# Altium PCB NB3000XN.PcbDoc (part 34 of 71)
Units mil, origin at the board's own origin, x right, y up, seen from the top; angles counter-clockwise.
Board outline 9527.56 x 6929.77 mil, 6 copper layers (Top Layer, GND+SHIELD, MidLayer1, MidLayer2, P2 - 3V3+5V0, Bottom Layer), stack 62.375 mil thick; 832 components, 1027 nets, 4655 pads, 4981 vias.
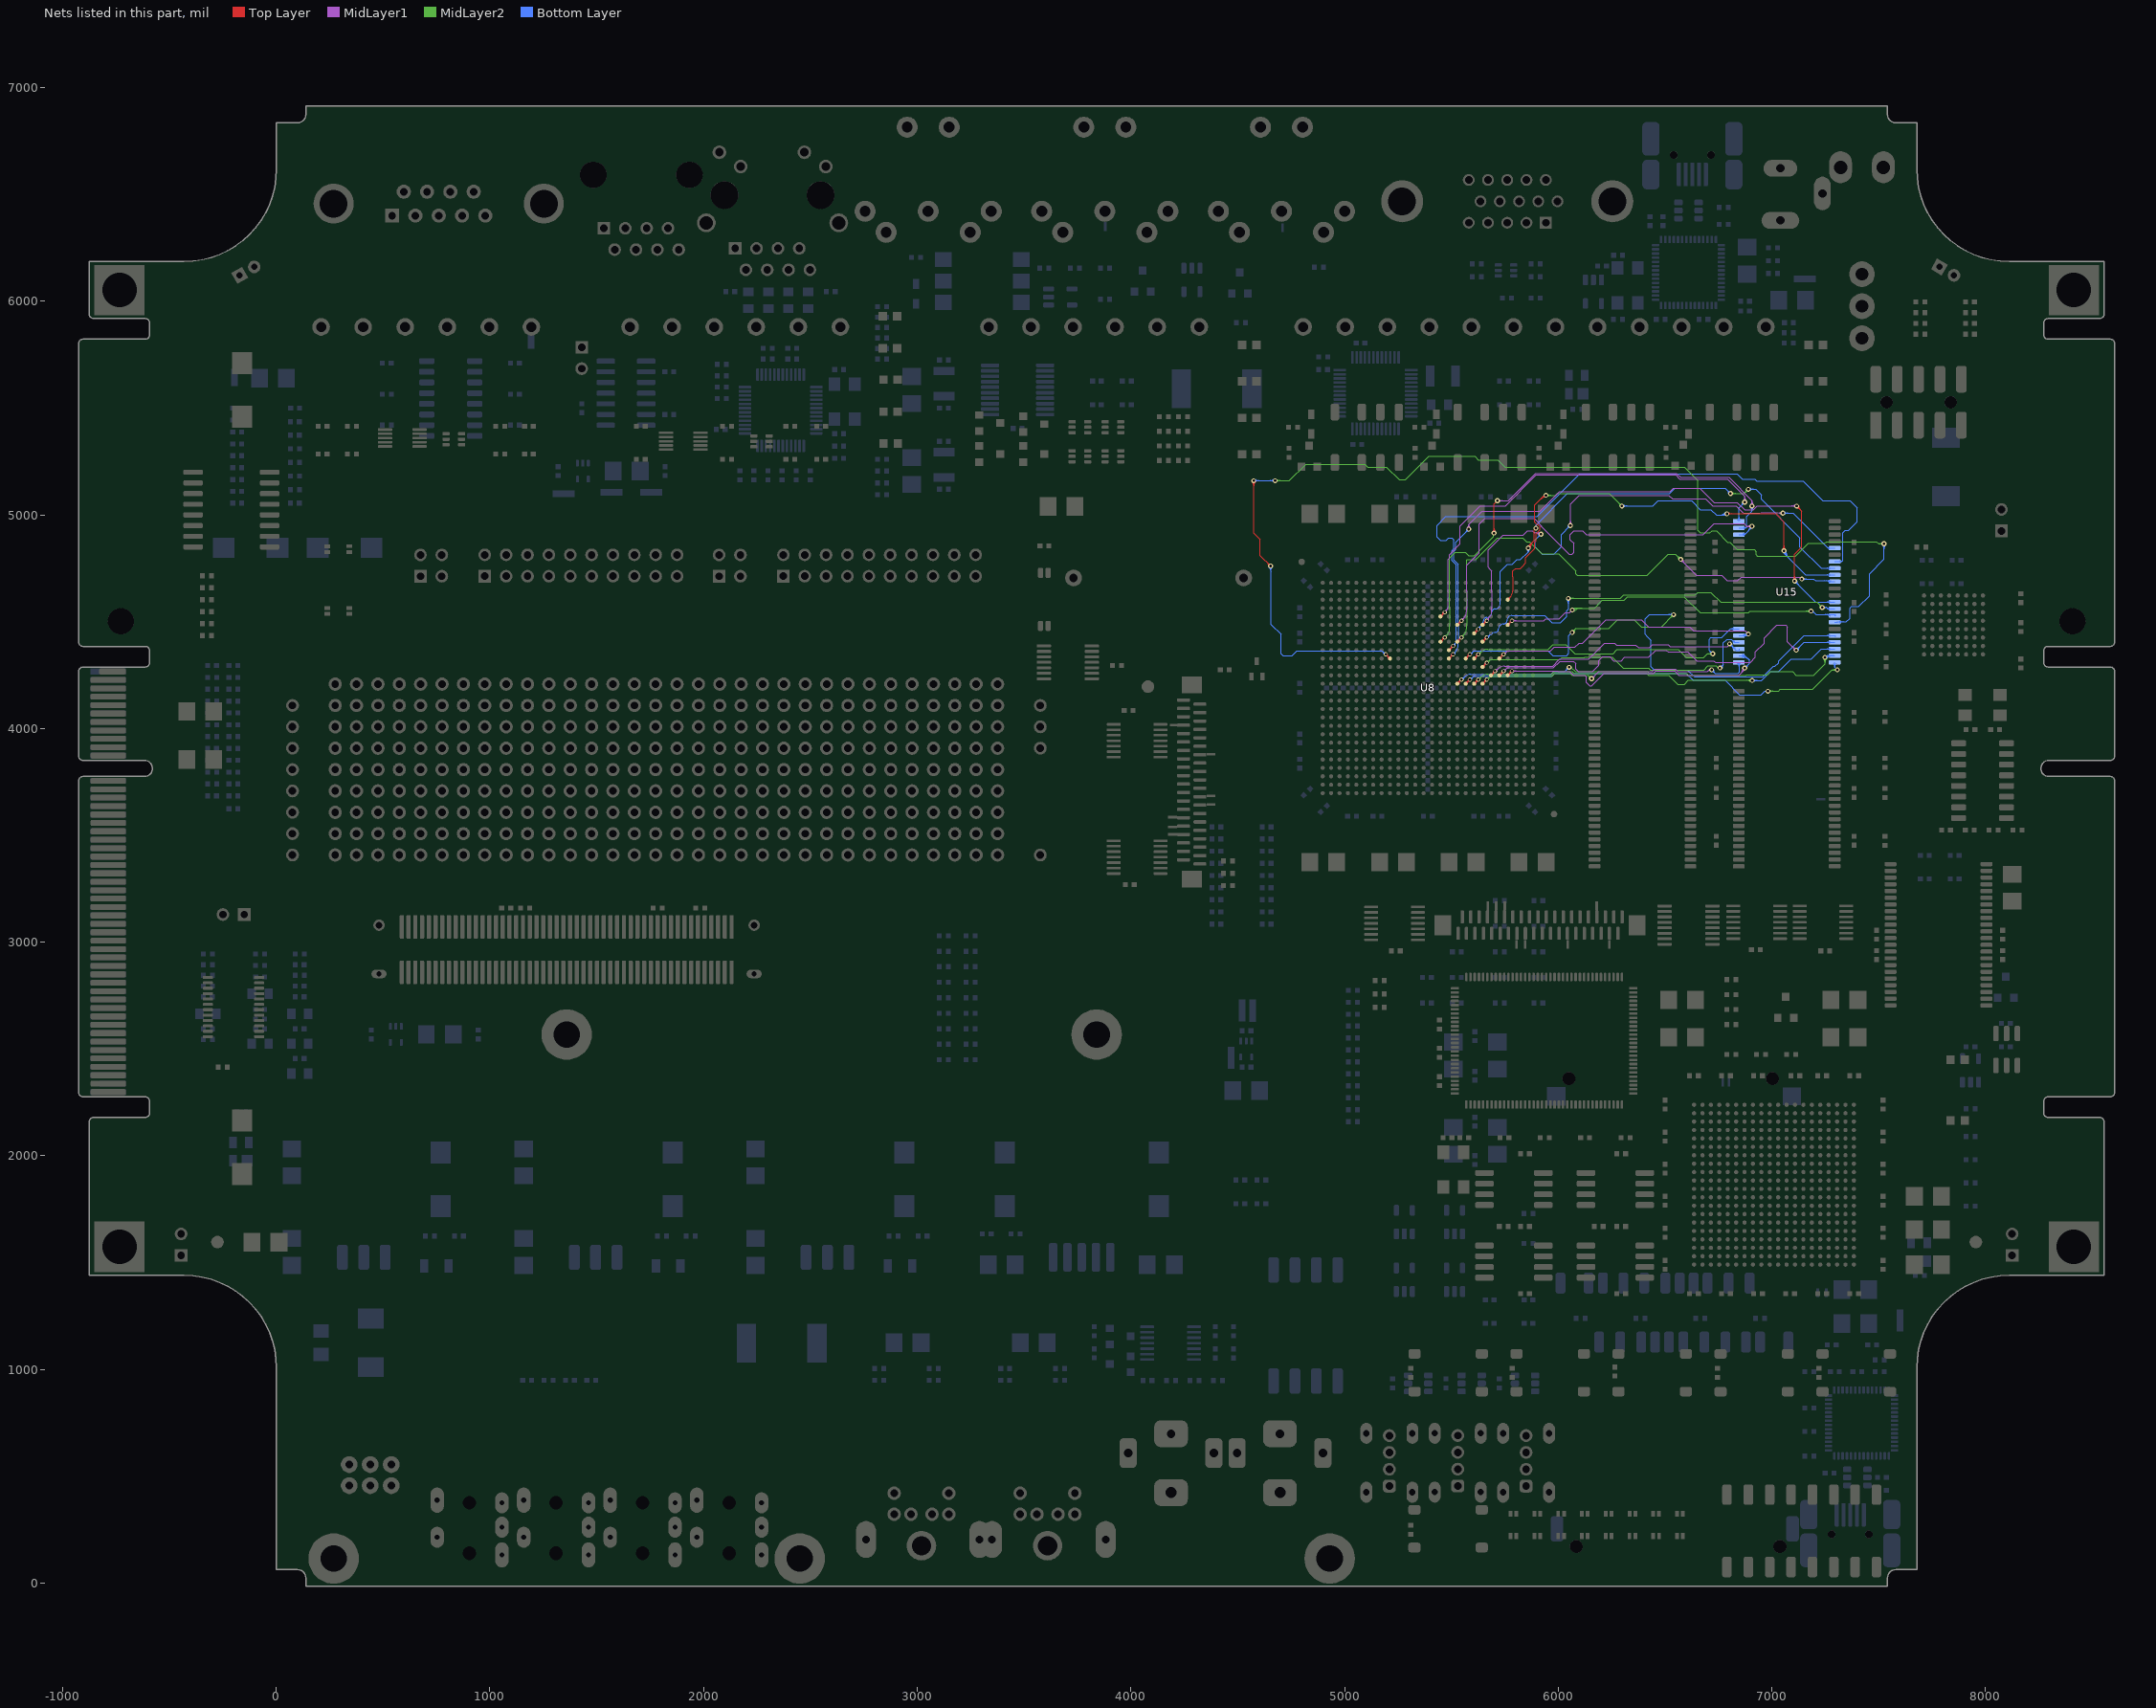
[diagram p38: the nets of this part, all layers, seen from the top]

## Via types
v1: diameter 23, hole 11.81, Top Layer to Bottom Layer, 3672 vias
v2: diameter 26, hole 11.81, Top Layer to Bottom Layer, 461 vias
v3: diameter 19, hole 11.81, Top Layer to Bottom Layer, tented both sides, 396 vias
v4: diameter 23.62, hole 11.81, Top Layer to Bottom Layer, 288 vias
v5: diameter 20, hole 11.81, Top Layer to Bottom Layer, 91 vias
v6: diameter 23, hole 11.81, Top Layer to Bottom Layer, tented both sides, 50 vias
v7: diameter 31, hole 11.81, Top Layer to Bottom Layer, 15 vias
v8: diameter 27.56, hole 11.81, Top Layer to Bottom Layer, tented both sides, 4 vias
v9: diameter 29, hole 11.81, Top Layer to Bottom Layer, 3 vias
v10: diameter 21, hole 11.81, Top Layer to Bottom Layer, 1 vias

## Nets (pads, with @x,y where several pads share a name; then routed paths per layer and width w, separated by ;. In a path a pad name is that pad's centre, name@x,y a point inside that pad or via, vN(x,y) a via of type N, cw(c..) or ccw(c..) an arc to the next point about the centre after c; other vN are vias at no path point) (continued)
DB_SRAM2.A4: U8.F20 U15.5 | length 2940.1
  Top Layer w4: U8.F20@5645.91,4485.28 v3(5665.59,4504.96) ; U8.F20@5645.91,4492.62 ccw(c5645.91,4510.34) 5658.44,4497.81 ccw(c5670.97,4485.28) U8.F20@5653.25,4485.28 ; U8.F20@5645.91,4492.78 ccw(c5645.91,4510.88) 5658.71,4498.08 ccw(c5671.51,4485.28) U8.F20@5653.41,4485.28 ; 5652.79,4492.16 cw(c5665.59,4479.35) 5665.59,4497.46 ccw(c5665.59,4479.35) 5652.79,4492.16 ; 5652.79,4492.16 ccw(c5639.98,4504.96) 5658.09,4504.96 cw(c5639.98,4504.96) 5652.79,4492.16
  MidLayer1 w4: v3@5664.29,4512.35 ccw(c5661.14,4530.18) 5675.98,4519.79 ; v3@5672.98,4506.26 cw(c5690.81,4509.41) 5675.98,4519.79 ; 5689.45,4581.77 5689.45,4567.84 ; 5896.15,4916.71 cw(c5896.15,4892.81) v1@5915.54,4906.78 ; 5903.96,4916.71 cw(c5903.96,4898.44) v1@5918.78,4909.12 ; v1@5912.29,4904.44 ccw(c5888.33,4887.17) 5888.33,4916.71 ; v1(5920,4910) 5920,4910.23 5913.52,4916.71 5888.33,4916.71 ; v1@6050.14,4956.76 ccw(c6032.37,4974.53) 6057.5,4974.53 ; v1@6052.97,4953.93 ccw(c6042.03,4964.87) 6057.5,4964.87 ; v1(6056.86,4950.04) 6057.5,4950.68 6057.5,5050.68 6098.52,5091.71 6518.17,5091.71 6534.84,5075.04 6690.19,5075.04 6723.52,5041.71 6831.86,5041.71 6865.86,5007.71 6944.52,5007.71 6948.52,5011.71 7030.04,5011.71 7033.37,5008.37 ; 6057.5,4961.77 ccw(c6068.58,4961.77) v1@6060.75,4953.93 ; 6057.5,4971.42 ccw(c6078.24,4971.42) v1@6063.57,4956.76 ; v1@7044.13,5002.85 ccw(c7033.38,4995.15) 7033.38,5008.37 ; v1@7044.13,5013.9 cw(c7033.38,5021.6) 7033.38,5008.37 ; v1(7051.86,5008.37) 7033.37,5008.37 ; 5675.98,4519.79 5683.06,4528.37 ccw(c5665.68,4544.59) 5689.45,4544.59 5689.45,4567.84 ; 5689.45,4567.84 5689.45,4641.96 5689.45,4661.38 5689.45,4710 5689.45,4720 5689.45,4724.74 5689.45,4737.45 5678.4,4748.5 5672.03,4754.87 5672.03,4835.25 5741.78,4905 5837.15,4905 5857.19,4925.04 5880,4925.04 5888.33,4916.71
  Bottom Layer w4: 5903.39,4893.62 cw(c5920,4877) v1@5920,4900.5 ; 5903.95,4894.18 ccw(c5888.13,4910) v1@5910.5,4910 ; 5910.21,4900.45 cw(c5920,4890.66) v1@5920,4904.5 ; 5910.77,4901.01 ccw(c5901.78,4910) v1@5914.5,4910 ; v1(5920,4910) 5920,4910.23 5892.61,4882.84 5892.61,4849.27 5925.17,4816.71 5979.88,4816.71 6015.52,4852.36 6015.52,4908.71 v1(6056.86,4950.04) ; v1@6047.36,4950.04 cw(c6024.42,4950.04) 6040.64,4933.82 cw(c6056.86,4917.61) v1@6056.86,4940.54 ; v1@6051.36,4950.04 cw(c6038.08,4950.04) 6047.47,4940.65 cw(c6056.86,4931.26) v1@6056.86,4944.54 ; v1(7051.86,5008.37) 7098.52,5008.37 7262.18,4844.72 ; v1@7055.75,5004.49 cw(c7065.14,4995.1) 7065.14,5008.37 cw(c7065.14,5021.65) v1@7055.75,5012.26 ; v1@7058.57,5001.66 cw(c7074.79,4985.44) 7074.79,5008.37 cw(c7074.79,5031.31) v1@7058.57,5015.09 ; U15.5@7270.13,4840.39 ccw(c7262.18,4835.27) 7262.18,4844.72 ; U15.5@7270.13,4849.06 cw(c7262.18,4854.18) 7262.18,4844.72 ; U15.5@7294.41,4844.72 7262.18,4844.72
DB_SRAM2.A5: U8.K18 U15.18 | length 2823.8
  Top Layer w4: U8.K18@5567.17,4327.8 v3(5586.85,4347.48) ; U8.K18@5567.17,4335.14 ccw(c5567.17,4352.86) 5579.7,4340.33 ccw(c5592.23,4327.8) U8.K18@5574.51,4327.8 ; U8.K18@5567.17,4335.3 ccw(c5567.17,4353.4) 5579.97,4340.6 ccw(c5592.77,4327.8) U8.K18@5574.67,4327.8 ; 5574.05,4334.68 cw(c5586.85,4321.87) 5586.85,4339.98 ccw(c5586.85,4321.87) 5574.05,4334.68 ; 5574.05,4334.68 ccw(c5561.24,4347.48) 5579.35,4347.48 cw(c5561.24,4347.48) 5574.05,4334.68
  MidLayer2 w4: v1(6065.19,4450.04) 6065.19,4451.04 6081.86,4467.71 ; v1@6065.19,4455.54 ccw(c6065.19,4466.4) 6072.87,4458.72 ; v1@6065.19,4459.54 ccw(c6065.19,4480.06) 6079.7,4465.55 ; v1@6070.69,4450.1 cw(c6085.85,4450.26) 6075.13,4460.98 ; v1@6074.69,4450.14 cw(c6099.16,4450.4) 6081.86,4467.71 ; v1@6530.69,4533.37 cw(c6507.76,4533.37) 6523.97,4517.16 cw(c6540.19,4500.94) v1@6540.19,4523.87 ; v1@6534.69,4533.37 cw(c6521.41,4533.37) 6530.8,4523.99 cw(c6540.19,4514.6) v1@6540.19,4527.87 ; v1(6540.19,4533.37) 6482.86,4476.04 6389.19,4476.04 6356.86,4508.37 6277.19,4508.37 6236.52,4467.71 6081.86,4467.71
  Bottom Layer w4: v3@5587.5,4354.95 ccw(c5589.08,4372.99) 5600.72,4359.12 ccw(c5612.36,4345.25) v3@5594.32,4346.83 ; 5600.43,4358.87 cw(c5610.36,4348.94) 5610.36,4362.99 5703.9,4362.99 5910,4362.99 5920,4362.99 5953.72,4362.99 5975,4341.71 6040.19,4341.71 6050,4351.52 6050,4434.85 v1(6065.19,4450.04) ; v1@6533.47,4526.66 ccw(c6517.26,4510.44) 6517.26,4533.37 ccw(c6517.26,4556.31) v1@6533.47,4540.09 ; v1@6536.3,4529.49 ccw(c6526.91,4520.1) 6526.91,4533.37 ccw(c6526.91,4546.65) v1@6536.3,4537.26 ; v1(6540.19,4533.37) 6428.37,4533.37 6407.72,4512.72 6407.72,4440.84 6415.23,4433.34 6435,4413.56 6435,4290 6450,4275 6604.88,4275 6637.17,4242.71 6957.86,4242.71 7006.86,4291.71 7015.19,4291.71 7031.86,4308.37 7031.86,4316.71 7141.26,4426.11 7150.42,4435.27 U15.18@7294.41,4435.27 7298.52,4435.28 7298.52,4433.37 U15.18@7294.41,4433.37 ; U15.18@7271.19,4429.62 ccw(c7257.54,4415.96) 7257.54,4435.27 ccw(c7257.54,4454.59) U15.18@7271.19,4440.93
DB_SRAM2.A6: U8.M22 U15.19 | length 2199.5
  Top Layer w4: U8.M22@5724.65,4249.06 v3(5744.33,4268.74) ; U8.M22@5724.65,4256.4 ccw(c5724.65,4274.12) 5737.18,4261.59 ccw(c5749.71,4249.06) U8.M22@5731.99,4249.06 ; U8.M22@5724.65,4256.56 ccw(c5724.65,4274.66) 5737.45,4261.86 ccw(c5750.25,4249.06) U8.M22@5732.15,4249.06 ; 5731.53,4255.94 cw(c5744.33,4243.13) 5744.33,4261.24 ccw(c5744.33,4243.13) 5731.53,4255.94 ; 5731.53,4255.94 ccw(c5718.72,4268.74) 5736.83,4268.74 cw(c5718.72,4268.74) 5731.53,4255.94
  MidLayer1 w4: v3@5744.98,4276.21 ccw(c5746.56,4294.25) 5758.2,4280.38 ccw(c5769.84,4266.51) v3@5751.8,4268.09 ; 5757.91,4280.13 cw(c5767.84,4270.2) 5767.84,4284.25 5861.38,4284.25 5910,4284.25 5920,4284.25 5978.06,4284.25 6007.86,4314.04 6072.52,4314.04 6081.86,4304.71 6081.86,4278.02 6093.5,4266.37 6161.19,4266.37 6190.19,4295.37 6190.19,4319.69 6205.5,4335 ; 6205.5,4335.71 6240.84,4335.71 6260.17,4316.37 6295.21,4316.37 6312.21,4333.37 6423.52,4333.37 6456.86,4366.71 6506.86,4366.71 6515.19,4358.37 6606.63,4358.37 6648.29,4316.71 6728.29,4316.71 6735.63,4309.37 6899.52,4309.37 6923.52,4333.37 6923.52,4358.37 6965.19,4400.04 6965.19,4425.04 7023.52,4483.37 7065.19,4483.37 7073.52,4475.04 7073.52,4407.04 v1(7113.86,4366.71) ; v1@7104.36,4366.71 ccw(c7081.42,4366.71) 7097.64,4382.93 ccw(c7113.86,4399.14) v1@7113.86,4376.21 ; v1@7108.36,4366.71 ccw(c7095.08,4366.71) 7104.47,4376.1 ccw(c7113.86,4385.49) v1@7113.86,4372.21
  Bottom Layer w4: v1(7113.86,4366.71) 7150.93,4403.78 U15.19@7293.97,4403.78 ; v1@7113.86,4372.21 ccw(c7113.86,4385.49) 7123.25,4376.1 ccw(c7132.64,4366.71) v1@7119.36,4366.71 ; v1@7113.86,4376.21 ccw(c7113.86,4399.14) 7130.07,4382.93 ccw(c7146.29,4366.71) v1@7123.36,4366.71 ; U15.19@7271.19,4398.12 ccw(c7257.54,4384.46) 7257.54,4403.78 ccw(c7257.54,4423.09) U15.19@7271.19,4409.44 ; U15.19@7293.97,4403.78 U15.19@7294.41,4403.78 U15.19@7293.97,4403.78
DB_SRAM2.A7: U8.N19 U15.20 | length 2062.7
  Top Layer w4: U8.N19@5606.54,4209.69 v3(5626.22,4229.37) ; U8.N19@5606.54,4217.03 ccw(c5606.54,4234.75) 5619.07,4222.22 ccw(c5631.6,4209.69) U8.N19@5613.88,4209.69 ; U8.N19@5606.54,4217.19 ccw(c5606.54,4235.29) 5619.34,4222.49 ccw(c5632.14,4209.69) U8.N19@5614.04,4209.69 ; 5613.42,4216.57 cw(c5626.22,4203.76) 5626.22,4221.87 ccw(c5626.22,4203.76) 5613.42,4216.57 ; 5613.42,4216.57 ccw(c5600.61,4229.37) 5618.72,4229.37 cw(c5600.61,4229.37) 5613.42,4216.57
  MidLayer2 w4: v3@5626.87,4236.84 ccw(c5628.45,4254.88) 5640.09,4241.01 ; v3@5633.69,4228.72 cw(c5651.73,4227.14) 5640.09,4241.01 ; 6422.96,4250 6422.92,4250.04 ; 6882.51,4226.04 cw(c6882.51,4199.69) v1@6901.14,4218.32 ; 6887.34,4226.04 ccw(c6887.34,4245.56) v1@6901.14,4231.76 ; 6892.16,4226.04 cw(c6892.16,4209.35) v1@6903.97,4221.15 ; v1(6907.86,4225.04) 6906.86,4226.04 6608.86,4226.04 6590.19,4207.37 6560.52,4207.37 6517.86,4250.04 6422.92,4250.04 ; 5640.09,4241.01 cw(c5669.6,4211.5) 5669.6,4253.23 5689.1,4253.23 5763.22,4253.23 5782.64,4253.23 5910,4253.23 5920,4253.23 5968.54,4253.23 5982.02,4266.71 6065.19,4266.71 6073.52,4258.37 6414.58,4258.37 6422.92,4250.04
  Bottom Layer w4: v1(6907.86,4225.04) 6952.19,4225.04 6993.52,4266.37 7031.52,4266.37 7090.19,4325.04 7184.62,4325.04 7231.86,4372.28 U15.20@7294.41,4372.28 ; v1@6911.75,4221.15 cw(c6921.14,4211.76) 6921.14,4225.04 cw(c6921.14,4238.32) v1@6911.75,4228.93 ; v1@6914.57,4218.32 cw(c6930.79,4202.11) 6930.79,4225.04 cw(c6930.79,4247.98) v1@6914.57,4231.76 ; U15.20@7271.19,4366.63 ccw(c7257.54,4352.97) 7257.54,4372.28 ccw(c7257.54,4391.6) U15.20@7271.19,4377.94
DB_SRAM2.A8: U8.N17 U15.21 | length 2255.6
  Top Layer w4: U8.N17@5527.8,4209.69 v3(5547.48,4229.37) ; U8.N17@5527.8,4217.03 ccw(c5527.8,4234.75) 5540.33,4222.22 ccw(c5552.86,4209.69) U8.N17@5535.14,4209.69 ; U8.N17@5527.8,4217.19 ccw(c5527.8,4235.29) 5540.6,4222.49 ccw(c5553.4,4209.69) U8.N17@5535.3,4209.69 ; 5534.68,4216.57 cw(c5547.48,4203.76) 5547.48,4221.87 ccw(c5547.48,4203.76) 5534.68,4216.57 ; 5534.68,4216.57 ccw(c5521.87,4229.37) 5539.98,4229.37 cw(c5521.87,4229.37) 5534.68,4216.57
  MidLayer2 w4: v1(6051.52,4287.04) 6059.19,4287.04 6079.52,4266.71 6370,4266.71 6417.56,4266.71 6425.9,4258.37 6599.86,4258.37 6609.86,4248.37 6879.52,4248.37 6881.86,4250.71 6977.86,4250.71 6993.86,4266.71 7096.19,4266.71 7112.86,4250.04 7195.19,4250.04 7248.52,4303.37 v1(7248.52,4333.37) ; v1@7241.81,4326.66 cw(c7225.59,4310.44) 7248.52,4310.44 cw(c7271.46,4310.44) v1@7255.24,4326.66 ; v1@7244.64,4329.49 cw(c7235.25,4320.1) 7248.52,4320.1 cw(c7261.8,4320.1) v1@7252.41,4329.49
  Bottom Layer w4: v3@5548.13,4236.84 ccw(c5549.71,4254.88) 5561.35,4241.01 ; v3@5554.95,4228.72 cw(c5572.99,4227.14) 5561.35,4241.01 ; v1@6042.02,4287.04 cw(c6019.09,4287.04) 6035.31,4270.82 cw(c6051.52,4254.61) v1@6051.52,4277.54 ; v1@6046.02,4287.04 cw(c6032.75,4287.04) 6042.13,4277.65 cw(c6051.52,4268.26) v1@6051.52,4281.54 ; v1(6051.52,4287.04) 6031.19,4266.71 5978.88,4266.71 5965.4,4253.23 5920,4253.23 5910,4253.23 5703.9,4253.23 5684.48,4253.23 5610.36,4253.23 5590.86,4253.23 ccw(c5590.86,4211.5) 5561.35,4241.01 ; v1@7246.76,4335.14 cw(c7260.38,4321.52) 7260.38,4340.79 ; v1(7248.52,4333.37) 7255.94,4340.79 U15.21@7294.41,4340.79 ; v1@7249.58,4332.31 cw(c7270.04,4311.86) U15.21@7270.04,4340.79 ; v1@7252.41,4329.49 cw(c7279.7,4302.2) U15.21@7279.7,4340.79 ; v1@7255.24,4326.66 cw(c7289.35,4292.55) U15.21@7289.35,4340.79 ; U15.21@7271.19,4335.13 ccw(c7257.54,4321.47) 7257.54,4340.79 ccw(c7257.54,4360.1) U15.21@7271.19,4346.44
DB_SRAM2.A9: U8.N18 U15.22 | length 2155.8
  Top Layer w4: U8.N18@5567.17,4209.69 v3(5586.85,4229.37) ; U8.N18@5567.17,4217.03 ccw(c5567.17,4234.75) 5579.7,4222.22 ccw(c5592.23,4209.69) U8.N18@5574.51,4209.69 ; U8.N18@5567.17,4217.19 ccw(c5567.17,4235.29) 5579.97,4222.49 ccw(c5592.77,4209.69) U8.N18@5574.67,4209.69 ; 5574.05,4216.57 cw(c5586.85,4203.76) 5586.85,4221.87 ccw(c5586.85,4203.76) 5574.05,4216.57 ; 5574.05,4216.57 ccw(c5561.24,4229.37) 5579.35,4229.37 cw(c5561.24,4229.37) 5574.05,4216.57
  MidLayer2 w4: v1(6981.86,4175.04) 7031.67,4175.04 7040,4183.37 7190.19,4183.37 7281.86,4275.04 v1(7306.86,4275.04) ; v1@6985.75,4171.15 cw(c6995.14,4161.76) 6995.14,4175.04 cw(c6995.14,4188.32) v1@6985.75,4178.93 ; v1@6988.57,4168.32 cw(c7004.79,4152.11) 7004.79,4175.04 cw(c7004.79,4197.98) v1@6988.57,4181.76 ; v1@7300.14,4268.32 ccw(c7283.92,4252.11) 7283.92,4275.04 ccw(c7283.92,4297.98) v1@7300.14,4281.76 ; v1@7302.97,4271.15 ccw(c7293.58,4261.76) 7293.58,4275.04 ccw(c7293.58,4288.32) v1@7302.97,4278.93
  Bottom Layer w4: v3@5587.5,4236.84 ccw(c5589.08,4254.88) 5600.72,4241.01 ccw(c5612.36,4227.14) v3@5594.32,4228.72 ; 5600.43,4240.76 cw(c5610.36,4230.83) 5610.36,4244.88 5703.9,4244.88 5910,4244.88 5920,4244.88 5924.74,4244.88 5968.36,4244.88 5981.86,4258.37 6598.88,4258.37 6631.21,4226.04 6780.86,4226.04 6848.52,4158.37 6950,4158.37 6966.67,4175.04 v1(6981.86,4175.04) ; U15.22@7288.75,4303.63 cw(c7275.1,4289.98) 7294.41,4289.98 cw(c7313.72,4289.98) U15.22@7300.07,4303.63 ; U15.22@7294.41,4309.29 7294.41,4287.49 v1(7306.86,4275.04)
DB_SRAM2.A10: U8.N20 U15.23 | length 1706.8
  Top Layer w4: U8.N20@5645.91,4209.69 v3(5665.59,4229.37) ; U8.N20@5645.91,4217.03 ccw(c5645.91,4234.75) 5658.44,4222.22 ccw(c5670.97,4209.69) U8.N20@5653.25,4209.69 ; U8.N20@5645.91,4217.19 ccw(c5645.91,4235.29) 5658.71,4222.49 ccw(c5671.51,4209.69) U8.N20@5653.41,4209.69 ; 5652.79,4216.57 cw(c5665.59,4203.76) 5665.59,4221.87 ccw(c5665.59,4203.76) 5652.79,4216.57 ; 5652.79,4216.57 ccw(c5639.98,4229.37) 5658.09,4229.37 cw(c5639.98,4229.37) 5652.79,4216.57
  MidLayer1 w4: v1(6156.86,4233.37) 6190.19,4266.71 6441.71,4266.71 6453.54,4278.54 6548.01,4278.54 6559.84,4266.71 6698.52,4266.71 6706.86,4275.04 v1(6718.19,4275.04) ; v1@6156.86,4238.87 ccw(c6156.86,4252.15) 6166.25,4242.76 ccw(c6175.64,4233.37) v1@6162.36,4233.37 ; v1@6156.86,4242.87 ccw(c6156.86,4265.81) 6173.07,4249.59 ccw(c6189.29,4233.37) v1@6166.36,4233.37 ; 6697.35,4265.53 cw(c6710.29,4252.6) v1@6716.36,4269.85 ; 6701.84,4270.02 cw(c6712.63,4259.24) v1@6717.69,4273.63 ; 6706.33,4274.52 cw(c6714.97,4265.88) v1@6719.02,4277.4
  MidLayer2 w4: v3@5666.24,4236.84 ccw(c5667.82,4254.88) 5679.46,4241.01 ccw(c5691.1,4227.14) v3@5673.06,4228.72 ; 5679.17,4240.76 cw(c5689.1,4230.83) 5689.1,4244.88 5782.64,4244.88 5910,4244.88 5920,4244.88 5971.5,4244.88 5985,4258.37 6056.86,4258.37 6065.19,4250.04 6115,4250.04 6140.23,4250 v1(6156.86,4233.37) ; v1@6147.36,4233.37 ccw(c6124.42,4233.37) 6140.64,4249.59 ccw(c6156.86,4265.81) v1@6156.86,4242.87 ; v1@6151.36,4233.37 ccw(c6138.08,4233.37) 6147.47,4242.76 ccw(c6156.86,4252.15) v1@6156.86,4238.87
  Bottom Layer w4: v1@6718.19,4265.54 cw(c6718.19,4242.61) 6734.41,4258.82 cw(c6750.63,4275.04) v1@6727.69,4275.04 ; v1@6718.19,4269.54 cw(c6718.19,4256.26) 6727.58,4265.65 cw(c6736.97,4275.04) v1@6723.69,4275.04 ; v1(6718.19,4275.04) 6734.52,4258.71 6841.29,4258.71 6848.52,4265.94 6848.52,4309.29 U15.23@6845.59,4309.29 ; U15.23@6839.93,4303.63 cw(c6819.19,4282.89) 6848.52,4282.89 ; U15.23@6842.76,4306.46 cw(c6828.85,4292.55) 6848.52,4292.55 ; 6848.52,4297.06 cw(c6857.82,4297.06) U15.23@6851.25,4303.63
DB_SRAM2.A11: U8.M23 U15.24 | length 1719.9
  Top Layer w4: U8.M23@5764.02,4249.06 v3(5783.7,4268.74) ; U8.M23@5764.02,4256.4 ccw(c5764.02,4274.12) 5776.55,4261.59 ccw(c5789.08,4249.06) U8.M23@5771.36,4249.06 ; U8.M23@5764.02,4256.56 ccw(c5764.02,4274.66) 5776.82,4261.86 ccw(c5789.62,4249.06) U8.M23@5771.52,4249.06 ; 5770.9,4255.94 cw(c5783.7,4243.13) 5783.7,4261.24 ccw(c5783.7,4243.13) 5770.9,4255.94 ; 5770.9,4255.94 ccw(c5758.09,4268.74) 5776.2,4268.74 cw(c5758.09,4268.74) 5770.9,4255.94
  MidLayer1 w4: v3(5783.7,4268.74) 5861.38,4268.74 5910,4268.74 5920,4268.74 5997.97,4268.74 6000,4266.71 6053.86,4266.71 6070.52,4250.04 6123.86,4250.04 6131.86,4242.04 6131.86,4216.71 6148.52,4200.04 6156.86,4200.04 6215.19,4258.37 6444.69,4258.37 6456.85,4270.54 6544.7,4270.54 6545.52,4269.71 6565.19,4250.04 6846.86,4250.04 6873.52,4276.71 v1(6873.52,4283.37) ; v3@5788.89,4263.55 cw(c5801.43,4251.01) 5801.43,4268.74 cw(c5801.43,4286.47) v3@5788.89,4273.93 ; v3@5789,4263.44 cw(c5801.81,4250.63) 5801.81,4268.74 cw(c5801.81,4286.85) v3@5789,4274.04 ; 6852.59,4255.78 ccw(c6824.99,4283.37) v1@6864.02,4283.37 ; 6859.42,4262.6 ccw(c6838.65,4283.37) v1@6868.02,4283.37 ; 6866.25,4269.43 ccw(c6852.31,4283.37) v1@6872.02,4283.37 ; 6868.69,4271.87 cw(c6873.52,4267.04) v1@6873.52,4273.87
  Bottom Layer w4: U15.24@6845.59,4340.79 6874.21,4340.79 6895,4320 6895,4304.85 v1(6873.52,4283.37) ; U15.24@6863.15,4332.79 cw(c6863.15,4286.76) 6895.69,4319.31 ; U15.24@6863.15,4336.79 cw(c6863.15,4300.42) 6888.86,4326.14 ; U15.24@6863.15,4340.79 cw(c6863.15,4314.08) 6882.04,4332.96 ; U15.24@6863.15,4344.79 cw(c6863.15,4327.73) 6875.21,4339.79 ; v1@6873.52,4288.87 ccw(c6873.52,4302.15) 6882.91,4292.76 ccw(c6892.3,4283.37) v1@6879.02,4283.37 ; v1@6873.52,4292.87 ccw(c6873.52,4315.81) 6889.74,4299.59 ccw(c6905.96,4283.37) v1@6883.02,4283.37
DB_SRAM2.A12: U8.M21 U15.25 | length 1505.3
  Top Layer w4: U8.M21@5685.28,4249.06 v3(5704.96,4268.74) ; U8.M21@5685.28,4256.4 ccw(c5685.28,4274.12) 5697.81,4261.59 ccw(c5710.34,4249.06) U8.M21@5692.62,4249.06 ; U8.M21@5685.28,4256.56 ccw(c5685.28,4274.66) 5698.08,4261.86 ccw(c5710.88,4249.06) U8.M21@5692.78,4249.06 ; 5692.16,4255.94 cw(c5704.96,4243.13) 5704.96,4261.24 ccw(c5704.96,4243.13) 5692.16,4255.94 ; 5692.16,4255.94 ccw(c5679.35,4268.74) 5697.46,4268.74 cw(c5679.35,4268.74) 5692.16,4255.94
  MidLayer1 w4: v3@5705.61,4276.21 ccw(c5707.19,4294.25) 5718.83,4280.38 ; v3@5712.43,4268.09 cw(c5730.47,4266.51) 5718.83,4280.38 ; 5781.77,4292.6 5767.84,4292.6 ; v1(6802.19,4396.71) 6802.19,4391.71 6793.69,4383.21 6524.3,4383.21 6515.8,4391.71 6441.88,4391.71 6428.54,4378.37 6375.84,4378.37 6363.17,4391.04 6273.52,4391.04 6265.19,4399.37 6217.5,4399.37 6143.17,4325.04 6007.52,4325.04 5975.09,4292.6 5920,4292.6 5910,4292.6 5861.38,4292.6 5841.96,4292.6 5767.84,4292.6 ; 5718.83,4280.38 cw(c5748.34,4250.87) 5748.34,4292.6 5767.84,4292.6
  Bottom Layer w4: v1@6802.19,4387.21 cw(c6802.19,4364.27) 6818.41,4380.49 cw(c6834.63,4396.71) v1@6811.69,4396.71 ; v1@6802.19,4391.21 cw(c6802.19,4377.93) 6811.58,4387.32 cw(c6820.97,4396.71) v1@6807.69,4396.71 ; v1(6802.19,4396.71) 6832.19,4366.71 6845.59,4366.71 6848.52,4366.71 6848.52,4372.28 U15.25@6845.59,4372.28 ; 6811.96,4386.94 ccw(c6828.03,4403.02) U15.25@6828.03,4380.28 ; 6815.38,4383.52 cw(c6804.14,4372.28) U15.25@6820.03,4372.28 ; 6818.79,4380.11 ccw(c6828.03,4389.36) U15.25@6828.03,4376.28
DB_SRAM2.A13: U8.L20 U15.26 | length 1585.2
  Top Layer w4: U8.L20@5645.91,4288.43 v3(5665.59,4308.11) ; U8.L20@5645.91,4295.77 ccw(c5645.91,4313.49) 5658.44,4300.96 ccw(c5670.97,4288.43) U8.L20@5653.25,4288.43 ; U8.L20@5645.91,4295.93 ccw(c5645.91,4314.03) 5658.71,4301.23 ccw(c5671.51,4288.43) U8.L20@5653.41,4288.43 ; 5652.79,4295.31 cw(c5665.59,4282.5) 5665.59,4300.61 ccw(c5665.59,4282.5) 5652.79,4295.31 ; 5652.79,4295.31 ccw(c5639.98,4308.11) 5658.09,4308.11 cw(c5639.98,4308.11) 5652.79,4295.31
  MidLayer2 w4: v3@5666.24,4315.58 ccw(c5667.82,4333.62) 5679.46,4319.75 ccw(c5691.1,4305.88) v3@5673.06,4307.46 ; 5679.17,4319.5 cw(c5689.1,4309.57) 5689.1,4323.62 5782.64,4323.62 5910,4323.62 5920,4323.62 5924.74,4323.62 6008.43,4323.62 6017.52,4332.71 6123.19,4332.71 6125.19,4334.71 6252.19,4334.71 6303.52,4283.37 6423.52,4283.37 6431.86,4275.04 6681.86,4275.04 6700.19,4293.37 6738.52,4293.37 6748.52,4283.37 v1(6757.52,4283.37)
  Bottom Layer w4: v1(6757.52,4283.37) 6773.52,4299.37 ; v1@6757.58,4288.87 ccw(c6757.7,4301.72) 6766.79,4292.64 ccw(c6775.87,4283.55) v1@6763.02,4283.43 ; v1@6757.62,4292.87 ccw(c6757.83,4315.07) 6773.52,4299.37 ; v1@6767.02,4283.47 cw(c6789.22,4283.68) 6773.52,4299.37 ; 6812.39,4414.66 ccw(c6821.68,4423.95) U15.26@6825.63,4411.41 ; 6817.05,4409.99 ccw(c6823.92,4416.86) U15.26@6826.83,4407.59 ; 6817.75,4409.29 cw(c6812.23,4403.78) U15.26@6820.03,4403.78 ; U15.26@6845.59,4403.78 6823.26,4403.78 6810,4417.04 6789.52,4417.04 6773.52,4401.04 6773.52,4299.37
DB_SRAM2.A14: U8.K22 U15.27 | length 1574.5
  Top Layer w4: U8.K22@5724.65,4327.8 v3(5744.33,4347.48) ; U8.K22@5724.65,4335.14 ccw(c5724.65,4352.86) 5737.18,4340.33 ccw(c5749.71,4327.8) U8.K22@5731.99,4327.8 ; U8.K22@5724.65,4335.3 ccw(c5724.65,4353.4) 5737.45,4340.6 ccw(c5750.25,4327.8) U8.K22@5732.15,4327.8 ; 5731.53,4334.68 cw(c5744.33,4321.87) 5744.33,4339.98 ccw(c5744.33,4321.87) 5731.53,4334.68 ; 5731.53,4334.68 ccw(c5718.72,4347.48) 5736.83,4347.48 cw(c5718.72,4347.48) 5731.53,4334.68
  MidLayer1 w4: v3@5744.98,4354.95 ccw(c5746.56,4372.99) 5758.2,4359.12 ccw(c5769.84,4345.25) v3@5751.8,4346.83 ; 5757.91,4358.87 cw(c5767.84,4348.94) 5767.84,4362.99 5861.38,4362.99 5910,4362.99 5920,4362.99 5964.39,4362.99 5982.11,4380.71 6079.19,4380.71 6098.52,4400.04 6115.19,4400.04 6223.52,4508.37 6390.19,4508.37 6422.52,4476.04 6615.19,4476.04 6632.86,4458.37 6874.52,4458.37 v1(6890.19,4442.71)
  Bottom Layer w4: U15.27@6845.59,4435.27 6882.76,4435.27 v1(6890.19,4442.71) ; U15.27@6849.31,4435.27 ccw(c6849.31,4483.59) v1@6883.47,4449.43 ; U15.27@6858.97,4435.27 ccw(c6858.97,4473.93) v1@6886.3,4446.6 ; U15.27@6868.62,4435.27 ccw(c6868.62,4464.27) v1@6889.13,4443.77 ; U15.27@6868.81,4429.62 cw(c6882.46,4415.96) 6882.46,4435.27 cw(c6882.46,4454.59) U15.27@6868.81,4440.93 ; 6878.28,4435.27 ccw(c6878.28,4454.62) v1@6891.96,4440.94
DB_SRAM2.A15: U8.F17 U15.42 | length 2387
  Top Layer w4: U8.F17@5527.8,4485.28 v3(5547.48,4504.96) ; U8.F17@5527.8,4492.62 ccw(c5527.8,4510.34) 5540.33,4497.81 ccw(c5552.86,4485.28) U8.F17@5535.14,4485.28 ; U8.F17@5527.8,4492.78 ccw(c5527.8,4510.88) 5540.6,4498.08 ccw(c5553.4,4485.28) U8.F17@5535.3,4485.28 ; 5534.68,4492.16 cw(c5547.48,4479.35) 5547.48,4497.46 ccw(c5547.48,4479.35) 5534.68,4492.16 ; 5534.68,4492.16 ccw(c5521.87,4504.96) 5539.98,4504.96 cw(c5521.87,4504.96) 5534.68,4492.16
  MidLayer1 w4: v3@5546.83,4512.43 ccw(c5545.25,4530.47) 5559.12,4518.83 ; v3@5554.95,4505.61 cw(c5572.99,4507.19) 5559.12,4518.83 ; 5571.34,4581.77 5571.34,4567.84 ; v1@6900.14,4939.99 ccw(c6883.92,4923.77) 6883.92,4946.71 ccw(c6883.92,4969.64) v1@6900.14,4953.43 ; v1@6902.97,4942.82 ccw(c6893.58,4933.43) 6893.58,4946.71 ccw(c6893.58,4959.99) v1@6902.97,4950.6 ; v1(6906.86,4946.71) 6882.92,4946.71 6871.25,4958.37 6728.86,4958.37 6678.86,4908.37 6131.86,4908.37 6115.19,4925.04 6073.52,4925.04 6056.86,4908.37 6056.86,4883.71 6073.52,4867.04 6073.52,4824.71 6065.52,4816.71 6051.52,4816.71 5921.81,4946.42 5921.81,4948.57 5887.01,4983.37 5658.37,4983.37 5631.02,4956.02 5631.02,4823.37 5571.34,4763.69 5571.34,4724.74 5571.34,4720 5571.34,4710 5571.34,4661.38 5571.34,4641.96 5571.34,4567.84 ; 5559.12,4518.83 ccw(c5529.61,4548.34) 5571.34,4548.34 5571.34,4567.84
  Bottom Layer w4: U15.42@6845.59,4907.72 6873.15,4907.72 6881.15,4915.72 ; U15.42@6863.15,4907.72 ccw(c6868.03,4915.04) 6874.25,4908.82 ; U15.42@6865.37,4911.04 ccw(c6870.79,4919.18) 6877.7,4912.27 ; U15.42@6867.59,4914.37 ccw(c6873.55,4923.32) 6881.15,4915.72 ; 6888.05,4924.23 ccw(c6865.57,4946.71) v1@6897.36,4946.71 ; 6894.88,4931.06 ccw(c6879.23,4946.71) v1@6901.36,4946.71 ; 6896.9,4933.08 cw(c6906.86,4923.13) v1@6906.86,4937.21 ; v1(6906.86,4946.71) 6906.86,4943.04 6881.15,4917.33 6881.15,4915.72
DB_SRAM2.A16: U8.H15 U15.43 | length 2748.8
  Top Layer w4: U8.H15@5449.06,4406.54 v3(5468.74,4426.22) ; U8.H15@5449.06,4413.88 ccw(c5449.06,4431.6) 5461.59,4419.07 ccw(c5474.12,4406.54) U8.H15@5456.4,4406.54 ; U8.H15@5449.06,4414.04 ccw(c5449.06,4432.14) 5461.86,4419.34 ccw(c5474.66,4406.54) U8.H15@5456.56,4406.54 ; v1@5693.28,4921.72 ccw(c5677.06,4937.93) 5700,4937.93 ccw(c5722.93,4937.93) v1@5706.72,4921.72 ; v1@5696.11,4918.89 ccw(c5686.72,4928.28) 5700,4928.28 ccw(c5713.28,4928.28) v1@5703.89,4918.89 ; v1@5698.52,4915.71 5699.23,4915 v1(5700,4915) 5700,5051.52 v1(5715.19,5066.71) ; 5455.94,4413.42 cw(c5468.74,4400.61) 5468.74,4418.72 ccw(c5468.74,4400.61) 5455.94,4413.42 ; 5455.94,4413.42 ccw(c5443.13,4426.22) 5461.24,4426.22 cw(c5443.13,4426.22) 5455.94,4413.42
  MidLayer1 w4: v1(5715.19,5066.71) 5766.52,5066.71 5894.52,5194.71 6553.54,5194.71 6572.21,5176.04 6798.52,5176.04 6906.86,5067.71 v1(6906.86,5041.71) ; v1@5719.08,5062.82 cw(c5728.47,5053.43) 5728.47,5066.71 cw(c5728.47,5079.99) v1@5719.08,5070.6 ; v1@5721.91,5059.99 cw(c5738.13,5043.77) 5738.13,5066.71 cw(c5738.13,5089.64) v1@5721.91,5073.43 ; v1@6900.14,5048.43 ccw(c6883.92,5064.64) 6906.86,5064.64 ccw(c6929.79,5064.64) v1@6913.57,5048.43 ; v1@6902.97,5045.6 ccw(c6893.58,5054.99) 6906.86,5054.99 ccw(c6920.14,5054.99) v1@6910.75,5045.6
  MidLayer2 w4: v3@5468.09,4433.69 ccw(c5466.51,4451.73) 5480.38,4440.09 ; v3@5476.21,4426.87 cw(c5494.25,4428.45) 5480.38,4440.09 ; 5492.6,4699.16 5492.6,4640.9 ; v1(5700,4915) 5699.23,4915 5698.52,4915.71 5698.52,4898.37 5608.86,4808.71 5581.88,4808.71 5565.54,4825.04 5518.86,4825.04 5492.6,4798.79 5492.6,4724.74 5492.6,4720 5492.6,4710 5492.6,4640.9 ; 5480.38,4440.09 ccw(c5450.87,4469.6) 5492.6,4469.6 5492.6,4489.1 5492.6,4563.22 5492.6,4582.64 5492.6,4640.9
  Bottom Layer w4: U15.43@6845.59,4939.21 6878.82,4939.21 ; U15.43@6869.63,4934.52 cw(c6878.82,4927.87) 6878.82,4939.21 ; U15.43@6869.63,4943.9 ccw(c6878.82,4950.55) 6878.82,4939.21 ; v1@6900.14,5034.99 cw(c6883.92,5018.77) 6906.86,5018.77 cw(c6929.79,5018.77) v1@6913.57,5034.99 ; v1@6902.97,5037.82 cw(c6893.58,5028.43) 6906.86,5028.43 cw(c6920.14,5028.43) v1@6910.75,5037.82 ; v1(6906.86,5041.71) 6906.86,5017.41 6881.15,4991.71 6881.15,4941.54 6878.82,4939.21
DB_SRAM2.A17: U8.E15 U15.44 | length 2342.1
  Top Layer w4: U8.E15@5449.06,4524.65 v3(5468.74,4544.33) ; U8.E15@5449.06,4531.99 ccw(c5449.06,4549.71) 5461.59,4537.18 ccw(c5474.12,4524.65) U8.E15@5456.4,4524.65 ; U8.E15@5449.06,4532.15 ccw(c5449.06,4550.25) 5461.86,4537.45 ccw(c5474.66,4524.65) U8.E15@5456.56,4524.65 ; 5455.94,4531.53 cw(c5468.74,4518.72) 5468.74,4536.83 ccw(c5468.74,4518.72) 5455.94,4531.53 ; 5455.94,4531.53 ccw(c5443.13,4544.33) 5461.24,4544.33 cw(c5443.13,4544.33) 5455.94,4531.53
  MidLayer1 w4: v3@5468.09,4551.8 ccw(c5466.51,4569.84) 5480.38,4558.2 ccw(c5494.25,4546.56) v3@5476.21,4544.98 ; 5480.13,4557.91 ccw(c5470.2,4567.84) 5484.25,4567.84 ; 5484.25,4581.77 5484.25,4567.84 ; v1@6866.81,5066.76 ccw(c6850.59,5082.98) 6873.52,5082.98 ccw(c6896.46,5082.98) v1@6880.24,5066.76 ; v1@6869.64,5063.93 ccw(c6860.25,5073.32) 6873.52,5073.32 ccw(c6886.8,5073.32) v1@6877.41,5063.93 ; v1(6873.52,5060.04) 6873.52,5086.04 6791.52,5168.04 6568.9,5168.04 6550.23,5186.71 5897.84,5186.71 5752.84,5041.71 5634.84,5041.71 5610.01,5016.88 5540.19,4947.06 5540.19,4864.33 5490.5,4814.64 5490.5,4797.37 5484.25,4791.12 5484.25,4724.74 5484.25,4720 5484.25,4710 5484.25,4661.38 5484.25,4567.84
  Bottom Layer w4: U15.44@6839.93,4976.36 ccw(c6826.28,4990.02) 6845.59,4990.02 ccw(c6864.9,4990.02) U15.44@6851.25,4976.36 ; U15.44@6845.59,4970.71 6845.59,5032.11 v1(6873.52,5060.04) ; v1@6864.02,5060.04 cw(c6841.09,5060.04) 6857.31,5043.82 cw(c6873.52,5027.61) v1@6873.52,5050.54 ; v1@6868.02,5060.04 cw(c6854.75,5060.04) 6864.14,5050.65 cw(c6873.52,5041.26) v1@6873.52,5054.54
DB_SRAM2.A18: U8.K19 U15.28 | length 1692.4
  Top Layer w4: U8.K19@5606.54,4327.8 v3(5626.22,4347.48) ; U8.K19@5606.54,4335.14 ccw(c5606.54,4352.86) 5619.07,4340.33 ccw(c5631.6,4327.8) U8.K19@5613.88,4327.8 ; U8.K19@5606.54,4335.3 ccw(c5606.54,4353.4) 5619.34,4340.6 ccw(c5632.14,4327.8) U8.K19@5614.04,4327.8 ; 5613.42,4334.68 cw(c5626.22,4321.87) 5626.22,4339.98 ccw(c5626.22,4321.87) 5613.42,4334.68 ; 5613.42,4334.68 ccw(c5600.61,4347.48) 5618.72,4347.48 cw(c5600.61,4347.48) 5613.42,4334.68
  MidLayer2 w4: v3@5626.87,4354.95 ccw(c5628.45,4372.99) 5640.09,4359.12 ; v3@5633.69,4346.83 cw(c5651.73,4345.25) 5640.09,4359.12 ; v1@6716.81,4343.32 ccw(c6700.59,4327.11) 6700.59,4350.04 ccw(c6700.59,4372.98) v1@6716.81,4356.76 ; v1@6719.64,4346.15 ccw(c6710.25,4336.76) 6710.25,4350.04 ccw(c6710.25,4363.32) v1@6719.64,4353.93 ; v1(6723.52,4350.04) 6698.67,4350.04 6680,4331.37 6600.52,4331.37 6562.19,4369.71 6275.52,4369.71 6256.86,4351.04 6108.86,4351.04 6106.86,4349.04 6078.19,4349.04 6035.52,4391.71 5974.19,4391.71 5953.83,4371.34 5920,4371.34 5910,4371.34 5782.64,4371.34 5763.22,4371.34 5689.1,4371.34 5669.6,4371.34 ccw(c5669.6,4329.61) 5640.09,4359.12
  Bottom Layer w4: v1@6714.02,4350.04 ccw(c6691.09,4350.04) 6707.31,4366.26 ccw(c6723.52,4382.48) v1@6723.52,4359.54 ; v1@6718.02,4350.04 ccw(c6704.75,4350.04) 6714.14,4359.43 ccw(c6723.52,4368.82) v1@6723.52,4355.54 ; v1(6723.52,4350.04) 6706.86,4366.71 6706.86,4418.04 6715.19,4426.37 6765.19,4426.37 6794.01,4455.19 6805.59,4466.77 U15.28@6845.59,4466.77 ; U15.28@6822.37,4461.11 ccw(c6808.72,4447.46) 6808.72,4466.77 ccw(c6808.72,4486.08) U15.28@6822.37,4472.43
DB_SRAM2.D0: U8.J16 U15.7 | length 3287.8
  Top Layer w4: U8.J16@5488.43,4367.17 v3(5508.11,4386.85) ; U8.J16@5488.43,4374.51 ccw(c5488.43,4392.23) 5500.96,4379.7 ccw(c5513.49,4367.17) U8.J16@5495.77,4367.17 ; U8.J16@5488.43,4374.67 ccw(c5488.43,4392.77) 5501.23,4379.97 ccw(c5514.03,4367.17) U8.J16@5495.93,4367.17 ; 5495.31,4374.05 cw(c5508.11,4361.24) 5508.11,4379.35 ccw(c5508.11,4361.24) 5495.31,4374.05 ; 5495.31,4374.05 ccw(c5482.5,4386.85) 5500.61,4386.85 cw(c5482.5,4386.85) 5495.31,4374.05
  Bottom Layer w4: v3@5507.46,4394.32 ccw(c5505.88,4412.36) 5519.75,4400.72 ccw(c5533.62,4389.08) v3@5515.58,4387.5 ; 5519.5,4400.43 ccw(c5509.57,4410.36) 5523.62,4410.36 5523.62,4503.9 5523.62,4710 5523.62,4720 5523.62,4765.63 5502.19,4787.06 5502.19,4832.02 5512.5,4842.33 5512.5,4882.25 5502.25,4892.5 5487.75,4892.5 5476.25,4881 5449.5,4881 5433.19,4897.31 5433.19,4951.37 5473.52,4991.71 5900.9,4991.71 6101.23,5192.04 6836.52,5192.04 6861.86,5166.71 6921.15,5166.71 6929.48,5158.37 7145.54,5158.37 7237.21,5066.71 7365.19,5066.71 7398.52,5033.37 7398.52,4967.71 7358.52,4927.71 7342.86,4927.71 7331.86,4916.71 7331.86,4786.73 7326.86,4781.73 ; U15.7@7294.41,4781.73 7326.86,4781.73 ; U15.7@7318.64,4777.32 cw(c7326.86,4771.88) 7326.86,4781.73 ; U15.7@7318.64,4786.15 ccw(c7326.86,4791.58) 7326.86,4781.73
DB_SRAM2.D1: U8.G19 U15.8 | length 2820.8
  Top Layer w4: U8.G19@5606.54,4445.91 v3(5626.22,4465.59) ; U8.G19@5606.54,4453.25 ccw(c5606.54,4470.97) 5619.07,4458.44 ccw(c5631.6,4445.91) U8.G19@5613.88,4445.91 ; U8.G19@5606.54,4453.41 ccw(c5606.54,4471.51) 5619.34,4458.71 ccw(c5632.14,4445.91) U8.G19@5614.04,4445.91 ; v4(5860,4845) 5860,4853.58 5888.02,4881.6 5888.02,4929.9 v4(5896,4937.88) ; v4@5861.81,4845 cw(c5886.89,4845) 5869.16,4862.74 ; v4@5865.81,4845 cw(c5900.55,4845) 5875.99,4869.57 ; v4@5869.81,4845 cw(c5914.21,4845) 5882.81,4876.39 ; 5613.42,4452.79 cw(c5626.22,4439.98) 5626.22,4458.09 ccw(c5626.22,4439.98) 5613.42,4452.79 ; 5613.42,4452.79 ccw(c5600.61,4465.59) 5618.72,4465.59 cw(c5600.61,4465.59) 5613.42,4452.79
  MidLayer2 w4: v1(6806.86,5100.04) 6870.19,5100.04 v1(6890.19,5120.04) ; v1@6810.75,5096.15 cw(c6820.14,5086.76) 6820.14,5100.04 cw(c6820.14,5113.32) v1@6810.75,5103.93 ; v1@6813.57,5093.32 cw(c6829.79,5077.11) 6829.79,5100.04 cw(c6829.79,5122.98) v1@6813.57,5106.76 ; v1@6880.69,5120.04 cw(c6857.76,5120.04) 6873.97,5103.82 cw(c6890.19,5087.61) v1@6890.19,5110.54 ; v1@6884.69,5120.04 cw(c6871.41,5120.04) 6880.8,5110.65 cw(c6890.19,5101.26) v1@6890.19,5114.54
  Bottom Layer w4: v3@5624.92,4472.98 ccw(c5621.77,4490.81) 5636.61,4480.42 ; v3@5633.61,4466.89 cw(c5651.44,4470.04) 5636.61,4480.42 ; v4@5855.17,4836.46 cw(c5850.49,4828.18) 5860,4828.18 ; v4(5860,4845) 5860,4828.18 ; v4@5864.83,4836.46 ccw(c5869.51,4828.18) 5860,4828.18 ; v4(5896,4937.88) 5896,4952.85 6043.19,5100.04 6521.15,5100.04 6546.15,5125.04 6781.86,5125.04 v1(6806.86,5100.04) ; v1@6797.36,5100.04 ccw(c6774.42,5100.04) 6790.64,5116.26 ccw(c6806.86,5132.48) v1@6806.86,5109.54 ; v1@6801.36,5100.04 ccw(c6788.08,5100.04) 6797.47,5109.43 ccw(c6806.86,5118.82) v1@6806.86,5105.54 ; v1(6890.19,5120.04) 6925,5120.04 6950.52,5094.52 6950.52,5073.04 7131.86,4891.71 7131.86,4850.04 7231.66,4750.23 U15.8@7294.41,4750.23 ; v1@6894.08,5116.15 cw(c6903.47,5106.76) 6903.47,5120.04 cw(c6903.47,5133.32) v1@6894.08,5123.93 ; v1@6896.91,5113.32 cw(c6913.13,5097.11) 6913.13,5120.04 cw(c6913.13,5142.98) v1@6896.91,5126.76 ; U15.8@7271.19,4744.58 ccw(c7257.54,4730.92) 7257.54,4750.23 ccw(c7257.54,4769.55) U15.8@7271.19,4755.89 ; 5636.61,4480.42 5643.03,4488.15 ccw(c5626.22,4504.96) 5649.99,4504.96 cw(c5665.59,4504.96) 5665.59,4520.56 ccw(c5665.59,4544.33) 5689.36,4544.33 cw(c5704.96,4544.33) 5704.96,4559.93 ccw(c5704.96,4583.7) 5728.73,4583.7 5728.73,4641.96 5728.73,4710 5728.73,4720 5728.73,4734.73 5763.16,4769.16 5784.31,4769.16 5806.86,4791.71 5823.52,4791.71 5860,4828.18
DB_SRAM2.D2: U8.C23 U15.9 | length 2892
  Top Layer w4: 5913.22,5070.07 cw(c5942.52,5040.76) v1@5942.52,5082.21 ; 5920.05,5076.9 cw(c5942.52,5054.42) v1@5942.52,5086.21 ; 5926.88,5083.73 cw(c5942.52,5068.08) v1@5942.52,5090.21 ; v1(5942.52,5091.71) 5934.86,5091.71 5890.19,5047.04 5890.19,4966.64 5901.14,4955.69 5903.38,4955.69 5913.81,4945.26 5913.81,4930.5 5896.02,4912.72 5896.02,4878.29 5890.19,4872.46 5890.19,4841.71 5848.52,4800.04 5848.52,4775.04 5834.22,4760.74 5834,4760.52 ; v1(6789.86,5005.37) 7018.19,5005.37 7056.86,4966.71 v1(7056.86,4832.37) ; v1@6793.75,5001.49 cw(c6803.14,4992.1) 6803.14,5005.37 cw(c6803.14,5018.65) v1@6793.75,5009.26 ; v1@6796.57,4998.66 cw(c6812.79,4982.44) 6812.79,5005.37 cw(c6812.79,5028.31) v1@6796.57,5012.09 ; v1@7050.14,4839.09 ccw(c7033.92,4855.31) 7056.86,4855.31 ccw(c7079.79,4855.31) v1@7063.57,4839.09 ; v1@7052.97,4836.26 ccw(c7043.58,4845.65) 7056.86,4845.65 ccw(c7070.14,4845.65) v1@7060.75,4836.26 ; 5776.55,4615.92 ccw(c5749.2,4643.27) 5787.88,4643.27 ; 5776.55,4615.92 ccw(c5749.2,4643.27) 5787.88,4643.27 ; 5776.55,4615.92 ccw(c5789.08,4603.39) 5771.36,4603.39 cw(c5789.08,4603.39) 5776.55,4615.92 ; 5776.55,4615.92 cw(c5764.02,4628.45) 5764.02,4610.73 ccw(c5764.02,4628.45) 5776.55,4615.92 ; 5787.88,4643.27 5787.88,4710 5787.88,4720 5787.88,4724.74 5787.88,4736.74 5789.88,4738.74 5800.14,4749 5822.48,4749 ; 5822.48,4749 5834,4760.52 ; 5822.48,4749 5834,4760.52
  MidLayer2 w4: v1(5942.52,5091.71) 5986.67,5091.71 5995,5100.04 6240.19,5100.04 v1(6298.52,5041.71) ; v1@5946.41,5087.82 cw(c5955.8,5078.43) 5955.8,5091.71 cw(c5955.8,5104.99) v1@5946.41,5095.6 ; v1@5949.24,5084.99 cw(c5965.46,5068.77) 5965.46,5091.71 cw(c5965.46,5114.64) v1@5949.24,5098.43 ; v1@6289.02,5041.71 ccw(c6266.09,5041.71) 6282.31,5057.93 ccw(c6298.52,5074.14) v1@6298.52,5051.21 ; v1@6293.02,5041.71 ccw(c6279.75,5041.71) 6289.14,5051.1 ccw(c6298.52,5060.49) v1@6298.52,5047.21
  Bottom Layer w4: v1(6298.52,5041.71) 6442.21,5041.71 6467.21,5066.71 6624.19,5066.71 6665.86,5025.04 6715.19,5025.04 6740.19,5000.04 6784.52,5000.04 v1(6789.86,5005.37) ; v1@6302.41,5037.82 cw(c6311.8,5028.43) 6311.8,5041.71 cw(c6311.8,5054.99) v1@6302.41,5045.6 ; v1@6305.24,5034.99 cw(c6321.46,5018.77) 6321.46,5041.71 cw(c6321.46,5064.64) v1@6305.24,5048.43 ; 6754.04,5000.04 ccw(c6754.04,5041.19) v1@6783.14,5012.09 ; 6763.7,5000.04 ccw(c6763.7,5031.53) v1@6785.97,5009.26 ; 6773.36,5000.04 ccw(c6773.36,5021.87) v1@6788.8,5006.44 ; v1@7054.36,4832.37 ccw(c7078.1,4832.37) 7061.31,4815.59 ; v1(7056.86,4832.37) 7056.86,4820.04 7158.16,4718.74 U15.9@7294.41,4718.74 ; v1@7058.36,4832.37 ccw(c7091.76,4832.38) 7068.14,4808.76 ; v1@7062.36,4832.37 ccw(c7105.41,4832.38) 7074.97,4801.93 ; v1@7066.36,4832.37 ccw(c7119.07,4832.38) 7081.8,4795.1 ; U15.9@7271.19,4713.08 ccw(c7257.54,4699.42) 7257.54,4718.74 ccw(c7257.54,4738.05) U15.9@7271.19,4724.4
DB_SRAM2.D3: U8.H17 U15.10 | length 2767
  Top Layer w4: U8.H17@5527.8,4406.54 v3(5547.48,4426.22) ; U8.H17@5527.8,4413.88 ccw(c5527.8,4431.6) 5540.33,4419.07 ccw(c5552.86,4406.54) U8.H17@5535.14,4406.54 ; U8.H17@5527.8,4414.04 ccw(c5527.8,4432.14) 5540.6,4419.34 ccw(c5553.4,4406.54) U8.H17@5535.3,4406.54 ; 5534.68,4413.42 cw(c5547.48,4400.61) 5547.48,4418.72 ccw(c5547.48,4400.61) 5534.68,4413.42 ; 5534.68,4413.42 ccw(c5521.87,4426.22) 5539.98,4426.22 cw(c5521.87,4426.22) 5534.68,4413.42
  MidLayer1 w4: v1@6573.52,4782.21 cw(c6573.52,4759.27) 6589.74,4775.49 cw(c6605.96,4791.71) v1@6583.02,4791.71 ; v1@6573.52,4786.21 cw(c6573.52,4772.93) 6582.91,4782.32 cw(c6592.3,4791.71) v1@6579.02,4791.71 ; v1(6573.52,4791.71) 6647.52,4717.71 6765.19,4717.71 6791.19,4691.71 6840.19,4691.71 6856.86,4708.37 7131.86,4708.37 v1(7140.19,4700.04)
  MidLayer2 w4: v3@5546.83,4433.69 ccw(c5545.25,4451.73) 5559.12,4440.09 ; v3@5554.95,4426.87 cw(c5572.99,4428.45) 5559.12,4440.09 ; 5571.34,4699.16 5571.34,4640.9 ; v1@6564.02,4791.71 ccw(c6541.09,4791.71) 6557.31,4807.93 ccw(c6573.52,4824.14) v1@6573.52,4801.21 ; v1@6568.02,4791.71 ccw(c6554.75,4791.71) 6564.14,4801.1 ccw(c6573.52,4810.49) v1@6573.52,4797.21 ; v1(6573.52,4791.71) 6548.52,4816.71 6515.54,4816.71 6415.54,4716.71 6090.19,4716.71 6081.86,4725.04 6081.86,4738.04 6002.52,4817.37 5924.13,4817.37 5866.46,4875.04 5851.88,4875.04 5835.21,4891.71 5714.48,4891.71 5614.78,4792 5573.31,4792 5571.34,4790.03 5571.34,4720 5571.34,4710 5571.34,4640.9 ; 5559.12,4440.09 ccw(c5529.61,4469.6) 5571.34,4469.6 5571.34,4489.1 5571.34,4563.22 5571.34,4582.64 5571.34,4640.9
  Bottom Layer w4: v1(7140.19,4700.04) 7196.67,4700.04 7205,4691.71 7276.84,4691.71 7276.84,4687.24 U15.10@7294.41,4687.24 ; v1@7144.08,4696.15 cw(c7153.47,4686.76) 7153.47,4700.04 cw(c7153.47,4713.32) v1@7144.08,4703.93 ; v1@7146.91,4693.32 cw(c7163.13,4677.11) 7163.13,4700.04 cw(c7163.13,4722.98) v1@7146.91,4706.76 ; 7246.76,4691.71 cw(c7246.76,4657.15) U15.10@7271.19,4681.59 ; 7256.41,4691.71 cw(c7256.41,4666.81) U15.10@7274.02,4684.41 ; 7266.07,4691.71 cw(c7266.07,4676.46) U15.10@7276.85,4687.24
DB_SRAM2.D4: U8.K16 U15.13 | length 3427.5
  Top Layer w4: U8.K16@5488.43,4327.8 v3(5508.11,4347.48) ; U8.K16@5488.43,4335.14 ccw(c5488.43,4352.86) 5500.96,4340.33 ccw(c5513.49,4327.8) U8.K16@5495.77,4327.8 ; U8.K16@5488.43,4335.3 ccw(c5488.43,4353.4) 5501.23,4340.6 ccw(c5514.03,4327.8) U8.K16@5495.93,4327.8 ; v1@7100.14,4697.09 ccw(c7083.92,4713.31) 7106.86,4713.31 ccw(c7129.79,4713.31) v1@7113.57,4697.09 ; v1@7102.97,4694.26 ccw(c7093.58,4703.65) 7106.86,4703.65 ccw(c7120.14,4703.65) v1@7110.75,4694.26 ; v1(7106.86,4690.37) 7106.86,4816.71 7140.19,4850.04 7140.19,5017.71 v1(7116.19,5041.71) ; v1@7116.19,5032.21 cw(c7116.19,5009.27) 7132.41,5025.49 cw(c7148.63,5041.71) v1@7125.69,5041.71 ; v1@7116.19,5036.21 cw(c7116.19,5022.93) 7125.58,5032.32 cw(c7134.97,5041.71) v1@7121.69,5041.71 ; 5495.31,4334.68 cw(c5508.11,4321.87) 5508.11,4339.98 ccw(c5508.11,4321.87) 5495.31,4334.68 ; 5495.31,4334.68 ccw(c5482.5,4347.48) 5500.61,4347.48 cw(c5482.5,4347.48) 5495.31,4334.68
  MidLayer1 w4: v1@5575.48,4940.42 ccw(c5562.48,4954.79) 5581.86,4954.79 ; v1@5578.17,4937.45 ccw(c5570.64,4945.77) 5581.86,4945.77 ccw(c5593.08,4945.77) v1@5585.55,4937.45 ; v1(5581.86,4933.37) 5581.86,4954.79 ; v1@5588.23,4940.42 cw(c5601.23,4954.79) 5581.86,4954.79 ; v1@7109.47,5034.99 ccw(c7093.26,5018.77) 7093.26,5041.71 ccw(c7093.26,5064.64) v1@7109.47,5048.43 ; v1@7112.3,5037.82 ccw(c7102.91,5028.43) 7102.91,5041.71 ccw(c7102.91,5054.99) v1@7112.3,5045.6 ; v1(7116.19,5041.71) 6931.86,5041.71 6913.86,5023.71 6872.48,5023.71 6837.82,5058.37 6729.48,5058.37 6662.82,5125.04 6540.19,5125.04 6523.52,5108.37 6006.86,5108.37 5915.19,5016.71 5643.78,5016.71 5619.95,4992.88 5581.86,4954.79
  Bottom Layer w4: v3@5507.46,4354.95 ccw(c5505.88,4372.99) 5519.75,4361.35 ; v3@5515.58,4348.13 cw(c5533.62,4349.71) 5519.75,4361.35 ; v1@5572.36,4933.37 cw(c5549.42,4933.37) 5565.64,4917.16 cw(c5581.86,4900.94) v1@5581.86,4923.87 ; v1@5576.36,4933.37 cw(c5563.08,4933.37) 5572.47,4923.99 cw(c5581.86,4914.6) v1@5581.86,4927.87 ; v1(5581.86,4933.37) 5520.5,4872.02 5520.5,4839.02 5510.86,4829.37 5510.86,4789.71 5531.97,4768.59 5531.97,4724.74 5531.97,4720 5531.97,4710 5531.97,4503.9 5531.97,4484.48 5531.97,4410.36 5531.97,4390.86 cw(c5490.24,4390.86) 5519.75,4361.35 ; v1@7106.86,4680.87 cw(c7106.86,4657.94) 7123.07,4674.16 cw(c7139.29,4690.37) v1@7116.36,4690.37 ; v1@7106.86,4684.87 cw(c7106.86,4671.6) 7116.25,4680.99 cw(c7125.64,4690.37) v1@7112.36,4690.37 ; v1(7106.86,4690.37) 7204.48,4592.75 U15.13@7294.41,4592.75 ; U15.13@7271.19,4587.1 ccw(c7257.54,4573.44) 7257.54,4592.75 ccw(c7257.54,4612.07) U15.13@7271.19,4598.41
DB_SRAM2.D5: U8.H20 U15.14 | length 2217.7
  Top Layer w4: U8.H20@5645.91,4406.54 v3(5665.59,4426.22) ; U8.H20@5645.91,4413.88 ccw(c5645.91,4431.6) 5658.44,4419.07 ccw(c5670.97,4406.54) U8.H20@5653.25,4406.54 ; U8.H20@5645.91,4414.04 ccw(c5645.91,4432.14) 5658.71,4419.34 ccw(c5671.51,4406.54) U8.H20@5653.41,4406.54 ; 5652.79,4413.42 cw(c5665.59,4400.61) 5665.59,4418.72 ccw(c5665.59,4400.61) 5652.79,4413.42 ; 5652.79,4413.42 ccw(c5639.98,4426.22) 5658.09,4426.22 cw(c5639.98,4426.22) 5652.79,4413.42
  MidLayer2 w4: v1(6047.52,4609.37) 6291.19,4609.37 6307.52,4625.71 6640.86,4625.71 6652.86,4637.71 6715.19,4637.71 6761.19,4591.71 7210.86,4591.71 v1(7235.86,4566.71) ; v1@6051.41,4605.49 cw(c6060.8,4596.1) 6060.8,4609.37 cw(c6060.8,4622.65) v1@6051.41,4613.26 ; v1@6054.24,4602.66 cw(c6070.46,4586.44) 6070.46,4609.37 cw(c6070.46,4632.31) v1@6054.24,4616.09 ; v1@7226.36,4566.71 ccw(c7203.42,4566.71) 7219.64,4582.93 ccw(c7235.86,4599.14) v1@7235.86,4576.21 ; v1@7230.36,4566.71 ccw(c7217.08,4566.71) 7226.47,4576.1 ccw(c7235.86,4585.49) v1@7235.86,4572.21
  Bottom Layer w4: v3@5666.89,4433.61 ccw(c5670.04,4451.44) 5680.42,4436.61 ; v3@5672.98,4424.92 cw(c5690.81,4421.77) 5680.42,4436.61 ; v1@6041.03,4602.44 cw(c6027.04,4587.48) 6047.52,4587.48 ; v1@6043.77,4605.36 cw(c6035.66,4596.7) 6047.52,4596.7 cw(c6059.39,4596.7) v1@6051.28,4605.36 ; v1(6047.52,4609.37) 6047.52,4587.48 ; v1@6054.01,4602.44 ccw(c6068.01,4587.48) 6047.52,4587.48 ; v1(7235.86,4566.71) 7255.74,4566.71 ; v1@7240.14,4563.25 cw(c7247.37,4557.41) 7247.37,4566.71 cw(c7247.37,4576) v1@7240.14,4570.16 ; v1@7243.25,4560.74 cw(c7255.74,4550.65) 7255.74,4566.71 ; v1@7243.25,4572.68 ccw(c7255.74,4582.77) 7255.74,4566.71 ; U15.14@7270.37,4556.57 ccw(c7261.19,4549.93) 7261.19,4561.26 ; U15.14@7270.37,4565.95 cw(c7261.19,4572.59) 7261.19,4561.26 ; U15.14@7294.41,4561.26 7261.19,4561.26 ; 5680.42,4436.61 5688.15,4443.03 cw(c5704.96,4426.22) 5704.96,4449.99 ccw(c5704.96,4465.59) 5720.56,4465.59 cw(c5744.33,4465.59) 5744.33,4489.36 ccw(c5744.33,4504.96) 5759.93,4504.96 cw(c5783.7,4504.96) 5783.7,4528.73 5841.96,4528.73 5900.22,4528.73 5910,4528.73 5920,4528.73 5936.27,4528.73 5970,4495 6010,4495 6040,4525 6040,4551.35 6050,4561.35 6050,4585 6047.52,4587.48 ; 7255.74,4566.71 7261.19,4561.26
DB_SRAM2.D6: U8.F23 U15.15 | length 2107.3
  Top Layer w4: U8.F23@5764.02,4485.28 v3(5783.7,4504.96) ; U8.F23@5764.02,4492.62 ccw(c5764.02,4510.34) 5776.55,4497.81 ccw(c5789.08,4485.28) U8.F23@5771.36,4485.28 ; U8.F23@5764.02,4492.78 ccw(c5764.02,4510.88) 5776.82,4498.08 ccw(c5789.62,4485.28) U8.F23@5771.52,4485.28 ; 5770.9,4492.16 cw(c5783.7,4479.35) 5783.7,4497.46 ccw(c5783.7,4479.35) 5770.9,4492.16 ; 5770.9,4492.16 ccw(c5758.09,4504.96) 5776.2,4504.96 cw(c5758.09,4504.96) 5770.9,4492.16
  MidLayer1 w4: v3(5783.7,4504.96) 5861.38,4504.96 5910,4504.96 5920,4504.96 5933.44,4504.96 5941.02,4512.54 6005.06,4512.54 6034.56,4542.04 6053.52,4542.04 v1(6066.19,4554.71) ; v3@5788.89,4499.77 cw(c5801.43,4487.23) 5801.43,4504.96 cw(c5801.43,4522.69) v3@5788.89,4510.15 ; 5801.81,4504.96 cw(c5801.81,4523.07) 5789,4510.26 ccw(c5801.81,4523.07) 5801.81,4504.96 ; 5801.81,4504.96 ccw(c5801.81,4486.85) 5789,4499.66 cw(c5801.81,4486.85) 5801.81,4504.96
  MidLayer2 w4: v1@6064.42,4556.48 cw(c6081.88,4539.02) 6081.88,4563.71 ; v1(6066.19,4554.71) 6075.19,4563.71 6170.52,4563.71 6206.86,4600.04 6307.86,4600.04 6325.52,4617.71 6589.19,4617.71 6665.19,4541.71 6890.19,4541.71 6898.52,4550.04 v1(7183.19,4550.04) ; v1@6067.25,4553.65 cw(c6091.54,4529.36) 6091.54,4563.71 ; v1@6070.08,4550.82 cw(c6101.2,4519.7) 6101.2,4563.71 ; v1@6072.91,4547.99 cw(c6110.85,4510.04) 6110.85,4563.71 ; v1@7176.47,4543.32 ccw(c7160.26,4527.11) 7160.26,4550.04 ccw(c7160.26,4572.98) v1@7176.47,4556.76 ; v1@7179.3,4546.15 ccw(c7169.91,4536.76) 7169.91,4550.04 ccw(c7169.91,4563.32) v1@7179.3,4553.93
  Bottom Layer w4: v1(7183.19,4550.04) 7190.19,4550.04 7206.86,4533.37 7294.41,4533.37 7298.52,4533.37 7298.52,4529.76 U15.15@7294.41,4529.76 ; v1@7183.23,4548.54 cw(c7183.8,4529.53) 7197.25,4542.98 ; v1@7183.35,4544.54 cw(c7184.18,4516.8) 7203.8,4536.43 ; v1@7192.69,4550.04 ccw(c7198.73,4550.04) 7194.46,4545.77 ; 7248.82,4533.37 cw(c7248.82,4501.73) U15.15@7271.19,4524.11 ; 7258.47,4533.37 cw(c7258.47,4511.39) U15.15@7274.02,4526.93 ; 7266.26,4533.37 ccw(c7266.26,4540.36) U15.15@7271.19,4535.42
DB_SRAM2.D7: U8.K9 U15.16 | length 5984.2
  Top Layer w4: v4@4568.06,5153.06 cw(c4551.31,5136.31) 4575,5136.31 cw(c4598.69,5136.31) v4@4581.94,5153.06 ; v4@4570.89,5155.89 cw(c4560.97,5145.97) 4575,5145.97 cw(c4589.03,5145.97) v4@4579.11,5155.89 ; v4@4573.52,5158.52 v4(4575,5160) 4575,4980 4575,4915 4605,4885 4605,4810.23 v1(4654.19,4761.04) ; v1@4644.69,4761.04 ccw(c4621.76,4761.04) 4637.97,4777.26 ccw(c4654.19,4793.48) v1@4654.19,4770.54 ; v1@4648.69,4761.04 ccw(c4635.41,4761.04) 4644.8,4770.43 ccw(c4654.19,4779.82) v1@4654.19,4766.54 ; v3(5193.15,4347.48) U8.K9@5212.83,4327.8 ; U8.K9@5205.33,4327.8 ccw(c5187.23,4327.8) 5200.03,4340.6 ccw(c5212.83,4353.4) U8.K9@5212.83,4335.3 ; U8.K9@5205.49,4327.8 ccw(c5187.77,4327.8) 5200.3,4340.33 ccw(c5212.83,4352.86) U8.K9@5212.83,4335.14 ; 5205.95,4334.68 ccw(c5193.15,4321.87) 5193.15,4339.98 cw(c5193.15,4321.87) 5205.95,4334.68 ; 5205.95,4334.68 cw(c5218.76,4347.48) 5200.65,4347.48 ccw(c5218.76,4347.48) 5205.95,4334.68
  MidLayer2 w4: v4(4675,5160) 4742.21,5160 4819.4,5237.19 5095.65,5237.19 5108.29,5224.54 5197.04,5224.54 5255.71,5165.87 5285.87,5165.87 5395.87,5275.87 5609.13,5275.87 5626.96,5258.04 5718.31,5258.04 5751.98,5224.37 6591.34,5224.37 6654.02,5161.69 6654.02,4927.46 6665.11,4916.37 6710.5,4916.37 6720,4925.87 6740.11,4925.87 6793.11,4872.87 6802.77,4872.87 6838.44,4837.21 6917.79,4837.21 6926.85,4828.15 6926.85,4813.15 6932.5,4807.5 7111.49,4807.5 7171.2,4867.21 7247.46,4867.21 7255.25,4875 7489.19,4875 7499.19,4865 v4(7525,4865) ; v4@4679.11,5155.89 cw(c4689.03,5145.97) 4689.03,5160 cw(c4689.03,5174.03) v4@4679.11,5164.11 ; v4@4681.94,5153.06 cw(c4698.69,5136.31) 4698.69,5160 cw(c4698.69,5183.69) v4@4681.94,5166.94 ; v4@7518.06,4858.06 ccw(c7501.31,4841.31) 7501.31,4865 ccw(c7501.31,4888.69) v4@7518.06,4871.94 ; v4@7520.89,4860.89 ccw(c7510.97,4850.97) 7510.97,4865 ccw(c7510.97,4879.03) v4@7520.89,4869.11
  Bottom Layer w4: v4(4575,5160) v4(4675,5160) ; v4@4579.11,5155.89 cw(c4589.03,5145.97) 4589.03,5160 cw(c4589.03,5174.03) v4@4579.11,5164.11 ; v4@4581.94,5153.06 cw(c4598.69,5136.31) 4598.69,5160 cw(c4598.69,5183.69) v4@4581.94,5166.94 ; v1@4647.67,4754.13 cw(c4633.43,4739.02) 4654.19,4739.02 ; v1@4650.42,4757.04 cw(c4642.17,4748.29) 4654.19,4748.29 cw(c4666.21,4748.29) v1@4657.96,4757.04 ; v1(4654.19,4761.04) 4654.19,4739.02 ; v1@4660.71,4754.13 ccw(c4674.95,4739.02) 4654.19,4739.02 ; v4@4668.06,5153.06 ccw(c4651.31,5136.31) 4651.31,5160 ccw(c4651.31,5183.69) v4@4668.06,5166.94 ; v4@4670.89,5155.89 ccw(c4660.97,5145.97) 4660.97,5160 ccw(c4660.97,5174.03) v4@4670.89,5164.11 ; 5179.57,4358.87 ccw(c5169.64,4348.94) 5169.64,4362.99 5076.1,4362.99 4870,4362.99 4860,4362.99 4777.99,4362.99 4755.37,4340.37 4713.19,4340.37 4703.52,4350.04 4703.52,4441.04 4656.86,4487.71 4656.86,4736.36 4654.19,4739.02 ; v3@5185.68,4346.83 ccw(c5167.64,4345.25) 5179.28,4359.12 ccw(c5190.92,4372.99) v3@5192.5,4354.95 ; U15.16@7294.41,4498.27 7306.86,4498.27 7306.86,4500.04 7348.52,4500.04 7365.19,4516.71 7365.19,4563.37 7373.52,4571.71 7406.86,4571.71 7456.86,4621.71 7456.86,4725.04 7525,4793.18 v4(7525,4865) ; U15.16@7314.8,4495.44 cw(c7325.91,4484.33) 7325.91,4500.04 ; U15.16@7317.63,4492.61 cw(c7335.57,4474.67) 7335.57,4500.04 ; U15.16@7317.63,4503.92 ccw(c7327,4513.3) 7327,4500.04 ; v4@7518.06,4858.06 cw(c7501.31,4841.31) 7525,4841.31 cw(c7548.69,4841.31) v4@7531.94,4858.06 ; v4@7520.89,4860.89 cw(c7510.97,4850.97) 7525,4850.97 cw(c7539.03,4850.97) v4@7529.11,4860.89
